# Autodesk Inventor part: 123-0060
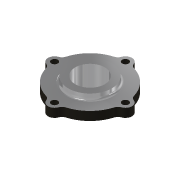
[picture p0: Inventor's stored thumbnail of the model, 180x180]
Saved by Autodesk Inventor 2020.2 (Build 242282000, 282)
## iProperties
Created: 2006-02
Part Number: 123-0060
Document SubType Name: Modeling
Designer: F.Stasiak
Description: Pokrywka typ1
Material: St 4S
Project: Przekładnia X51
Mass: 230.763 g
Surface Area: 113.991 cm^2
Volume: 29.3966 cm^3
Density: 7.85 g/cm^3
Appearance: Brąz armatni (nowy/polerowany)
Manager: www.cadconsulting.pl
Company: Fabian Stasiak CAD Consulting
Author: F.Stasiak
Subject: Zbiór ćwiczeń. Autodesk Inventor 2020. Kurs podstawowy
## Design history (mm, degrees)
sketch "Szkic1"
  geometry: C1 r 32.5 at (0, -38.423); A1 r 23.5 centre (0, -38.423) between (0, -14.923) and (0, -61.923) reference
  constraints: 1 centre point, 1 coincident
  dimensions: "d0" = 65 diameter of C1
extrude "Wyciągnięcie proste1" new body sketch "Szkic1" distance "d1" = 8; taper "d2" = 0 deg
sketch "Szkic2"
  geometry: C1 r 16.02 at (0, 0) reference
extrude "Wyciągnięcie proste2" join sketch "Szkic2" distance "d3" = 9.6; taper "d4" = 0 deg
sketch "Szkic4"
  geometry: C1 r 12.5 at (0, 0) reference; C2 r 13.5 at (0, 0)
  constraints: 1 centre point, 1 coincident
  dimensions: "d30" = 27 diameter of C2
extrude "Wyciągnięcie proste4" cut sketch "Szkic4" extent not by distance; stored distance "d7" = 6.5; taper "d8" = 0 deg
fillet "Zaokrąglenie1" dims "d9" = 5
sketch "Szkic5"
  geometry: L1 (0, 0)-(0, -32.5); C1 r 6 at (0, -32.5)
  constraints: 2 end point, 1 centre point, 1 coincident, 1 vertical, 1 vertical alignment, 1 other
  dimensions: "d10" = 12 diameter of C1
extrude "Wyciągnięcie proste5" join sketch "Szkic5" stored distance "d11" = 6.5; taper "d12" = 0 deg
hole "Otwór1" diameter "d19" = 6; stored, may be unused: countersink angle "d23" = 90 deg, drill point angle "d25" = 118 deg; dims "d17" = 10, "d18" = 10, "d20" = 6, "d21" = 4, "d22" = 2, "d24" = 8
fillet "Zaokrąglenie3" dims "d26" = 5
sketch "Szkic7"
  geometry: C1 r 13.5 at (0, -38.423) reference; C2 r 13.5 at (0, -38.423) reference; C3 r 20 at (0, -38.423)
  constraints: 1 centre point
  dimensions: "d31" = 40 diameter of C3
extrude "Wyciągnięcie proste7" join sketch "Szkic7" distance "d32" = 5; taper "d33" = 0 deg
fillet "Zaokrąglenie4" dims "d34" = 2
pattern_circular "Szyk kołowy2" dims angle "d36" = 360 deg
node "Bryła1"
node "Korpusy bryłowe"
node "Korpusy powierzchniowe"
node "Odniesienie1"
node "Odniesienie2"
node "Odniesienie4"
node "Pętla rzutowana1"
